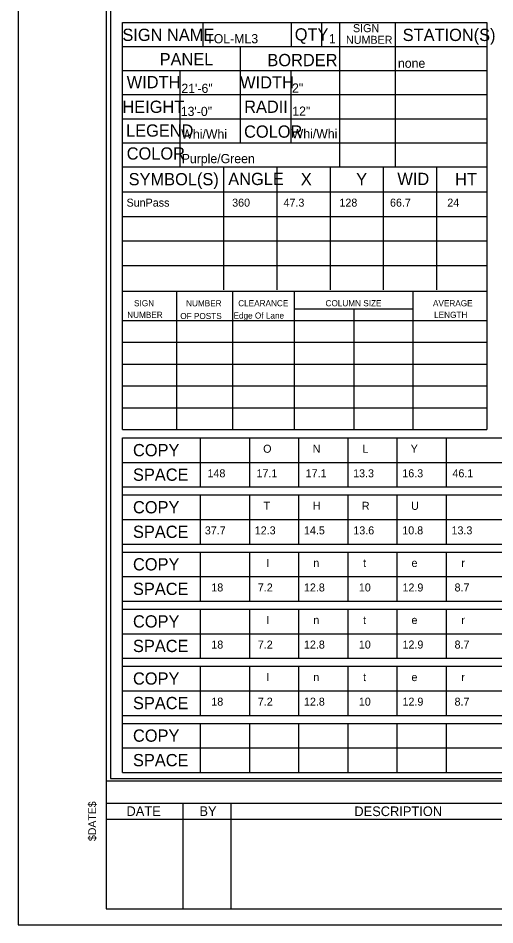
# Model space of a CAD drawing. Extents: x 119523 to 121850, y -23542 to -19972.
# Drawn here: x 119523 to 119943, y -23523 to -22723 of the extents above; entities that cross this region are included whole.
import ezdxf

# ---------------------------------------------------------------- set-up
doc = ezdxf.new("R2010")
doc.units = 0
for name, color, linetype in [('GSDims', 7, 'Continuous'), ('GSSign', 7, 'Continuous'), ('PlotBorder_dp', 7, 'Continuous'), ('SheetBorder_dp', 7, 'Continuous'), ('SheetLines_dp', 7, 'Continuous'), ('SheetLinesMisc2_dp', 7, 'Continuous'), ('TextMinor', 7, 'Continuous'), ('TextMisc', 7, 'Continuous')]:
    doc.layers.add(name, color=color, linetype=linetype)

msp = doc.modelspace()

# ---------------------------------------------------------------- linework, layer by layer
at = {"layer": 'PlotBorder_dp'}
msp.add_lwpolyline([(119522.87, -23522.86), (121850.2, -23522.86), (121850.2, -22027.72), (119522.87, -22027.72)], close=True, dxfattribs=at)
at = {"layer": 'SheetBorder_dp'}
for p, q in [((119600.45, -22041.83), (119600.45, -23508.75)), ((119600.45, -23395.91), (121772.62, -23395.91)), ((119600.45, -23508.75), (121772.62, -23508.75))]:
    msp.add_line(p, q, dxfattribs=at)
at = {"layer": 'SheetLines_dp'}
for p, q in [((119600.45, -23415.66), (120412.9, -23415.66)), ((119668.15, -23415.66), (119668.15, -23508.75)), ((119710.47, -23415.66), (119710.47, -23508.75)), ((119600.45, -23429.76), (120412.9, -23429.76))]:
    msp.add_line(p, q, dxfattribs=at)
at = {"layer": 'SheetLinesMisc2_dp'}
for p, q in [((119604.34, -22045.17), (119604.34, -23393.68)), ((119614.74, -23086.05), (119614.74, -22727.17)), ((119614.74, -22727.17), (119935.95, -22727.17)), ((119685.54, -22727.17), (119685.54, -22748.36)), ((119763.62, -22727.17), (119763.62, -22748.36)), ((119790.29, -22727.17), (119790.29, -22748.36)), ((119806.19, -22727.17), (119806.19, -22854.36)), ((119855.07, -22727.17), (119855.07, -22854.36)), ((119935.95, -22727.17), (119935.95, -23086.05)), ((119614.74, -22748.36), (119935.95, -22748.36)), ((119718.55, -22748.36), (119718.55, -22833.38)), ((119614.74, -22769.56), (119935.95, -22769.56)), ((119665.5, -22769.56), (119665.5, -22854.36)), ((119763.35, -22769.79), (119763.35, -22833.38)), ((119614.74, -22790.76), (119935.95, -22790.76)), ((119614.74, -22811.96), (119935.95, -22811.96)), ((119614.74, -22833.16), (119733.87, -22833.16)), ((119718.55, -22833.38), (119806.19, -22833.38)), ((119806.19, -22833.16), (119935.95, -22833.16)), ((119614.74, -22854.36), (119935.95, -22854.36)), ((119703.94, -22854.77), (119703.94, -22963)), ((119750.88, -22854.77), (119750.88, -22963)), ((119797.81, -22854.77), (119797.81, -22963)), ((119844.74, -22854.77), (119844.74, -22963)), ((119891.68, -22854.77), (119891.68, -22963)), ((119614.81, -22876.42), (119935.95, -22876.42)), ((119614.81, -22898.07), (119935.95, -22898.07)), ((119614.81, -22919.71), (119935.95, -22919.71)), ((119614.81, -22941.35), (119935.95, -22941.35)), ((119614.74, -22964.04), (119935.95, -22964.04)), ((119662.4, -22964.04), (119662.4, -23086.05)), ((119711.67, -22964.04), (119711.67, -23086.05)), ((119766.07, -22964.04), (119766.07, -23086.05)), ((119870.82, -22964.04), (119870.82, -23086.05)), ((119766.07, -22979.55), (119870.75, -22979.55)), ((119818.65, -22979.55), (119818.65, -23086.05)), ((119614.74, -22989.91), (119935.95, -22989.91)), ((119614.74, -23009.13), (119935.95, -23009.13)), ((119614.74, -23028.36), (119935.95, -23028.36)), ((119614.74, -23047.59), (119935.95, -23047.59)), ((119614.74, -23066.82), (119935.95, -23066.82)), ((119614.74, -23086.05), (119935.95, -23086.05)), ((119614.73, -23093.43), (120680.14, -23093.43)), ((119614.73, -23388.43), (119614.73, -23093.43)), ((119683.31, -23093.43), (119683.31, -23136.72)), ((119726.66, -23093.43), (119726.66, -23136.72)), ((119770, -23093.43), (119770, -23136.72)), ((119813.33, -23093.43), (119813.33, -23136.72)), ((119856.67, -23093.43), (119856.67, -23136.72)), ((119900.01, -23093.43), (119900.01, -23136.72)), ((119614.73, -23115.06), (120680.14, -23115.06)), ((119614.73, -23136.72), (120680.14, -23136.72)), ((119614.73, -23143.78), (120680.14, -23143.78)), ((119683.31, -23143.78), (119683.31, -23187.06)), ((119726.66, -23143.78), (119726.66, -23187.06)), ((119770, -23143.78), (119770, -23187.06)), ((119813.33, -23143.78), (119813.33, -23187.06)), ((119856.67, -23143.78), (119856.67, -23187.06)), ((119900.01, -23143.78), (119900.01, -23187.06)), ((119614.73, -23165.42), (120680.14, -23165.42)), ((119614.73, -23187.06), (120680.14, -23187.06)), ((119614.73, -23194.12), (120680.14, -23194.12)), ((119683.31, -23194.12), (119683.31, -23237.41)), ((119726.66, -23194.12), (119726.66, -23237.41)), ((119770, -23194.12), (119770, -23237.41)), ((119813.33, -23194.12), (119813.33, -23237.41)), ((119856.67, -23194.12), (119856.67, -23237.41)), ((119900.01, -23194.12), (119900.01, -23237.41)), ((119614.73, -23215.76), (120680.14, -23215.76)), ((119614.73, -23237.41), (120680.14, -23237.41)), ((119614.73, -23244.46), (120680.14, -23244.46)), ((119683.31, -23244.46), (119683.31, -23287.75)), ((119726.66, -23244.46), (119726.66, -23287.75)), ((119770, -23244.46), (119770, -23287.75)), ((119813.33, -23244.46), (119813.33, -23287.75)), ((119856.67, -23244.46), (119856.67, -23287.75)), ((119900.01, -23244.46), (119900.01, -23287.75)), ((119614.73, -23266.09), (120680.14, -23266.09)), ((119614.73, -23287.75), (120680.14, -23287.75)), ((119614.73, -23294.81), (120680.14, -23294.81)), ((119683.31, -23294.81), (119683.31, -23338.09)), ((119726.66, -23294.81), (119726.66, -23338.09)), ((119770, -23294.81), (119770, -23338.09)), ((119813.33, -23294.81), (119813.33, -23338.09)), ((119856.67, -23294.81), (119856.67, -23338.09)), ((119900.01, -23294.81), (119900.01, -23338.09)), ((119614.73, -23316.46), (120680.14, -23316.46)), ((119614.73, -23338.09), (120680.14, -23338.09)), ((119614.73, -23345.15), (120680.14, -23345.15)), ((119683.31, -23345.15), (119683.31, -23388.43)), ((119726.66, -23345.15), (119726.66, -23388.43)), ((119770, -23345.15), (119770, -23388.43)), ((119813.33, -23345.15), (119813.33, -23388.43)), ((119856.67, -23345.15), (119856.67, -23388.43)), ((119900.01, -23345.15), (119900.01, -23388.43)), ((119614.73, -23366.79), (120680.14, -23366.79)), ((119604.34, -23393.68), (121770.65, -23393.68)), ((119614.73, -23388.43), (120680.14, -23388.43))]:
    msp.add_line(p, q, dxfattribs=at)

# ---------------------------------------------------------------- texts
at = {"layer": 'GSDims'}
for s, height, p in [('SunPass', 7.058, (119618.43, -22889.51)), ('360', 7.058, (119711.52, -22889.51)), ('47.3', 7.058, (119756.78, -22889.51)), ('128', 7.058, (119806.06, -22889.51)), ('66.7', 7.058, (119850.64, -22889.51)), ('24', 7.058, (119901.12, -22889.51)), ('O', 7.06, (119738.84, -23106.53)), ('N', 7.06, (119782.52, -23106.53)), ('L', 7.06, (119826.21, -23106.53)), ('Y', 7.06, (119868.89, -23106.53)), ('148', 7.058, (119689.78, -23128.17)), ('17.1', 7.058, (119732.96, -23128.17)), ('17.1', 7.058, (119776.31, -23128.17)), ('13.3', 7.058, (119818.14, -23128.17)), ('16.3', 7.058, (119861.49, -23128.17)), ('46.1', 7.058, (119905.68, -23128.17)), ('T', 7.06, (119739.17, -23156.87)), ('H', 7.06, (119782.52, -23156.87)), ('R', 7.06, (119825.87, -23156.87)), ('U', 7.06, (119869.22, -23156.87)), ('37.7', 7.058, (119687.42, -23178.52)), ('12.3', 7.058, (119731.44, -23178.52)), ('14.5', 7.058, (119774.79, -23178.52)), ('13.6', 7.058, (119818.31, -23178.52)), ('10.8', 7.058, (119861.49, -23178.52)), ('13.3', 7.058, (119904.84, -23178.52)), ('I', 7.06, (119741.53, -23207.22)), ('n', 7.06, (119783.03, -23207.22)), ('t', 7.06, (119826.88, -23207.22)), ('e', 7.06, (119869.56, -23207.22)), ('r', 7.06, (119913.58, -23207.22)), ('18', 7.058, (119693.14, -23228.86)), ('7.2', 7.058, (119734.13, -23228.86)), ('12.8', 7.058, (119774.79, -23228.86)), ('10', 7.058, (119823.18, -23228.86)), ('12.9', 7.058, (119861.66, -23228.86)), ('8.7', 7.058, (119907.53, -23228.86)), ('I', 7.06, (119741.53, -23257.57)), ('t', 7.06, (119826.88, -23257.57)), ('n', 7.06, (119783.03, -23257.57)), ('e', 7.06, (119869.56, -23257.57)), ('r', 7.06, (119913.58, -23257.57)), ('18', 7.058, (119693.14, -23279.21)), ('7.2', 7.058, (119734.13, -23279.21)), ('12.8', 7.058, (119774.79, -23279.21)), ('10', 7.058, (119823.18, -23279.21)), ('12.9', 7.058, (119861.66, -23279.21)), ('8.7', 7.058, (119907.53, -23279.21)), ('I', 7.06, (119741.53, -23307.91)), ('n', 7.06, (119783.03, -23307.91)), ('t', 7.06, (119826.88, -23307.91)), ('e', 7.06, (119869.56, -23307.91)), ('r', 7.06, (119913.58, -23307.91)), ('18', 7.058, (119693.14, -23329.55)), ('7.2', 7.058, (119734.13, -23329.55)), ('12.8', 7.058, (119774.79, -23329.55)), ('10', 7.058, (119823.18, -23329.55)), ('12.9', 7.058, (119861.66, -23329.55)), ('8.7', 7.058, (119907.53, -23329.55))]:
    msp.add_text(s, height=height, dxfattribs=at).set_placement(p)
at = {"layer": 'GSSign'}
for s, height, p in [('TOL-ML3', 8.099, (119688.67, -22745.45)), ('1', 8.1, (119796.78, -22745.47)), ('none', 8.099, (119857.64, -22767.07)), ('21\'-6"', 8.099, (119666.77, -22789.23)), ('2"', 8.099, (119764.29, -22788.93)), ('13\'-0"', 8.099, (119666.21, -22809.57)), ('12"', 8.099, (119764.5, -22809.35)), ('Whi/Whi', 8.099, (119666.68, -22829.55)), ('Whi/Whi', 8.099, (119763.95, -22829.23)), ('Purple/Green', 8.099, (119667.04, -22851.2))]:
    msp.add_text(s, height=height, dxfattribs=at).set_placement(p)
at = {"layer": 'TextMinor'}
for s, height, p in [('SIGN', 7.058, (119817.99, -22735.66)), ('SIGN NAME', 10.799, (119614.74, -22743.4)), ('QTY', 10.799, (119766.7, -22743.04)), ('NUMBER', 7.058, (119811.85, -22745.93)), ('STATION(S)', 10.799, (119861.81, -22743.46)), ('PANEL', 10.799, (119647.58, -22764.93)), ('BORDER', 10.799, (119742.56, -22765.66)), ('WIDTH', 10.799, (119618.55, -22785.11)), ('WIDTH', 10.799, (119718.55, -22785.33)), ('HEIGHT', 10.799, (119614.74, -22806.84)), ('RADII', 10.799, (119722.09, -22806.8)), ('LEGEND', 10.799, (119617.99, -22827.81)), ('COLOR', 10.799, (119722.01, -22828.72)), ('COLOR', 10.799, (119618.55, -22848.03)), ('SYMBOL(S)', 10.799, (119620.27, -22870.69)), ('ANGLE', 10.799, (119708.07, -22870.47)), ('WID', 10.799, (119857.14, -22870.47)), ('X', 10.8, (119771.99, -22870.69)), ('Y', 10.8, (119820.8, -22870.69)), ('HT', 10.799, (119908.01, -22870.67)), ('SIGN', 5.4, (119625.04, -22977.35)), ('NUMBER', 5.4, (119670.88, -22977.42)), ('CLEARANCE', 5.4, (119716.85, -22977.38)), ('COLUMN SIZE', 5.3996, (119793.8, -22977.38)), ('AVERAGE', 5.4, (119888.51, -22977.38)), ('NUMBER', 5.4, (119618.99, -22987.62)), ('OF POSTS', 5.4, (119665.78, -22988.64)), ('Edge Of Lane', 5.3996, (119712.69, -22988.25)), ('LENGTH', 5.4, (119889.53, -22987.62)), ('COPY', 10.799, (119624.08, -23109.61)), ('SPACE', 10.799, (119624.08, -23131.26)), ('COPY', 10.799, (119624.08, -23159.98)), ('SPACE', 10.799, (119624.08, -23181.62)), ('COPY', 10.799, (119624.08, -23210.3)), ('SPACE', 10.799, (119624.08, -23231.95)), ('COPY', 10.799, (119624.08, -23260.66)), ('SPACE', 10.799, (119624.08, -23282.29)), ('COPY', 10.799, (119624.08, -23311.01)), ('SPACE', 10.799, (119624.08, -23332.65)), ('COPY', 10.799, (119624.08, -23361.35)), ('SPACE', 10.799, (119624.08, -23382.98))]:
    msp.add_text(s, height=height, dxfattribs=at).set_placement(p)
msp.add_text('$DATE$', height=6.912, rotation=90, dxfattribs=at).set_placement((119591.56, -23448.92))
at = {"layer": 'TextMisc'}
for s, height, rotation, p in [('DATE', 8.463, 359.86925, (119618.36, -23426.8)), ('DESCRIPTION', 8.4613, 0.04975, (119819.22, -23426.94))]:
    msp.add_text(s, height=height, rotation=rotation, dxfattribs=at).set_placement(p)
msp.add_text('BY', height=8.463, dxfattribs=at).set_placement((119682.68, -23426.8))

doc.saveas('drawing.dxf')
